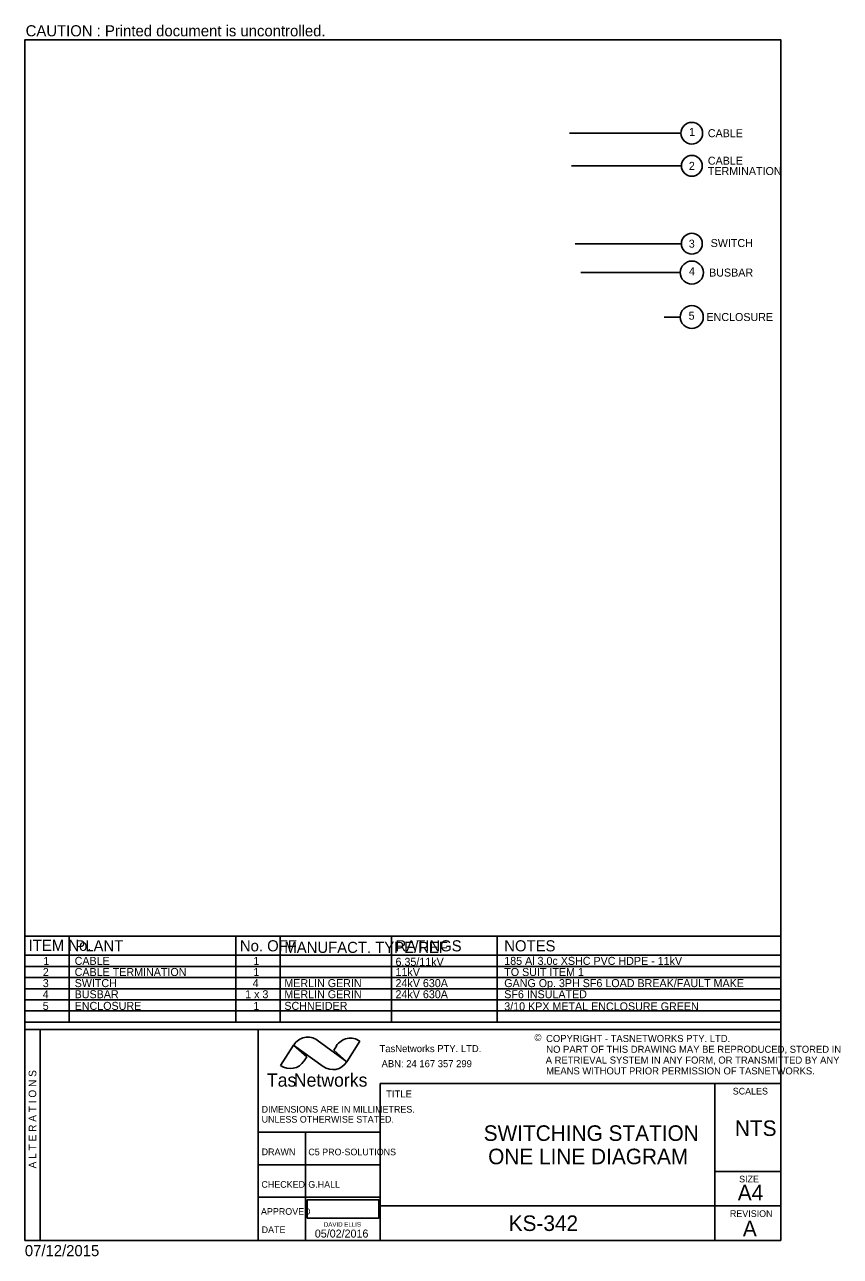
# Model space of a CAD drawing. Extents: x -190 to -7, y 10 to 287.
import ezdxf

# ---------------------------------------------------------------- set-up
doc = ezdxf.new("R2010")
doc.units = 0
for name, color, linetype in [('A4 BORDER TITLE BLOCK', 7, 'Continuous'), ('Default', 7, 'Continuous'), ('DRAWING', 7, 'Continuous')]:
    doc.layers.add(name, color=color, linetype=linetype)

# ---------------------------------------------------------------- blocks, each defined once
blk = doc.blocks.new('POINT_DISPLAY')
at = {"layer": 'Default'}
blk.add_line((0, 0), (0, 0), dxfattribs=at)
blk = doc.blocks.new('David Ellis')
at = {"layer": 'Default'}
blk.add_lwpolyline([(0.38, 5.03), (16.52, 5.03), (16.52, 9.1), (0.38, 9.1)], close=True, dxfattribs=at)
for s, height, p in [('DAVID ELLIS', 1, (4.15, 3.1)), ('05/02/2016', 1.8, (2.12, 0.65))]:
    blk.add_text(s, height=height, dxfattribs=at).set_placement(p)

msp = doc.modelspace()

# ---------------------------------------------------------------- linework, layer by layer
at = {"layer": 'A4 BORDER TITLE BLOCK'}
for p, q in [((-20, 60.93), (-190, 60.93)), ((-186.58, 13.5), (-186.58, 60.93)), ((-137.52, 13.5), (-137.52, 60.93)), ((-117.6, 53.69), (-124.25, 58.52)), ((-117.6, 53.69), (-124.25, 58.52)), ((-117.6, 53.69), (-124.25, 58.52)), ((-117.6, 53.69), (-114.66, 58.29)), ((-117.6, 53.69), (-114.66, 58.29)), ((-117.6, 53.69), (-114.66, 58.29)), ((-129.55, 57.45), (-132.49, 52.85)), ((-129.55, 57.45), (-132.49, 52.85)), ((-129.55, 57.45), (-132.49, 52.85)), ((-129.55, 57.45), (-122.9, 52.62)), ((-129.55, 57.45), (-126.61, 54.82)), ((-126.61, 54.82), (-129.55, 57.45)), ((-129.55, 57.45), (-122.9, 52.62)), ((-129.55, 57.45), (-122.9, 52.62)), ((-129.55, 57.45), (-126.61, 54.82)), ((-119.95, 57.22), (-120.53, 56.32)), ((-119.95, 57.22), (-120.53, 56.32)), ((-119.95, 57.22), (-120.53, 56.32)), ((-120.53, 56.32), (-117.6, 53.69)), ((-120.53, 56.32), (-117.6, 53.69)), ((-120.53, 56.32), (-117.6, 53.69)), ((-127.19, 53.92), (-126.61, 54.82)), ((-127.19, 53.92), (-126.61, 54.82)), ((-127.19, 53.92), (-126.61, 54.82)), ((-110.13, 48.77), (-20, 48.77)), ((-110.13, 48.77), (-110.13, 13.5)), ((-34.83, 13.5), (-34.83, 48.77)), ((-137.52, 37.82), (-110.13, 37.82)), ((-126.91, 37.82), (-126.91, 13.5)), ((-137.52, 30.53), (-110.13, 30.53)), ((-34.83, 29.02), (-20, 29.02)), ((-137.52, 23.23), (-110.13, 23.23)), ((-34.83, 21.26), (-110.13, 21.26)), ((-34.83, 21.26), (-20, 21.26)), ((-20, 13.5), (-190, 13.5))]:
    msp.add_line(p, q, dxfattribs=at)
msp.add_lwpolyline([(-190, 13.5), (-190, 283.5), (-20, 283.5), (-20, 13.5)], dxfattribs=at)
for centre, start_param, end_param in [((-126.39, 55.16), 5.685005, 7.255802), ((-126.39, 55.16), 5.685005, 7.255802), ((-126.39, 55.16), 5.685005, 7.255802), ((-116.8, 54.93), 5.685005, 7.255802), ((-116.8, 54.93), 5.685005, 7.255802), ((-116.8, 54.93), 5.685005, 7.255802), ((-130.34, 56.21), 2.543413, 4.114209), ((-130.34, 56.21), 2.543413, 4.114209), ((-130.34, 56.21), 2.543413, 4.114209), ((-120.75, 55.98), 2.543413, 4.114209), ((-120.75, 55.98), 2.543413, 4.114209), ((-120.75, 55.98), 2.543413, 4.114209)]:
    msp.add_ellipse(centre, major_axis=(0, 4.07), ratio=0.938106, start_param=start_param, end_param=end_param, dxfattribs=at)
at = {"layer": 'Default'}
for p, q in [((-42.44, 262.5), (-67.5, 262.5)), ((-42.34, 255.16), (-67.04, 255.16)), ((-42.35, 237.65), (-66.25, 237.65)), ((-42.59, 231.16), (-65, 231.16)), ((-42.59, 221.16), (-46.25, 221.16)), ((-180.05, 81.9), (-180.05, 62.62)), ((-142.55, 81.9), (-142.55, 62.62)), ((-132.55, 81.9), (-132.55, 62.62)), ((-107.55, 81.9), (-107.55, 62.62)), ((-83.8, 81.9), (-83.8, 62.62))]:
    msp.add_line(p, q, dxfattribs=at)
for centre, radius in [((-40.01, 262.5), 2.43), ((-40, 255.16), 2.34), ((-40, 237.65), 2.35), ((-40, 231.16), 2.59), ((-40.01, 221.16), 2.58)]:
    msp.add_circle(centre, radius, dxfattribs=at)
at = {"layer": 'DRAWING'}
for p, q in [((-190.05, 81.9), (-20.05, 81.9)), ((-190.05, 77.62), (-20.05, 77.62)), ((-190.05, 75.12), (-20.05, 75.12)), ((-190.05, 72.62), (-20.05, 72.62)), ((-190.05, 70.12), (-20.05, 70.12)), ((-190.05, 67.62), (-20.05, 67.62)), ((-190.05, 65.12), (-20.05, 65.12)), ((-190.05, 62.62), (-20.05, 62.62))]:
    msp.add_line(p, q, dxfattribs=at)

# ---------------------------------------------------------------- block references
at = {"layer": 'A4 BORDER TITLE BLOCK', "xscale": 1.7000000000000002, "yscale": 1.5882352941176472}
msp.add_blockref('POINT_DISPLAY', (-132.03, 52.53), dxfattribs=at)
msp.add_blockref('POINT_DISPLAY', (-132.03, 52.53), dxfattribs=at)
at = {"layer": 'Default'}
msp.add_blockref('David Ellis', (-126.91, 13.5), dxfattribs=at)

# ---------------------------------------------------------------- texts
at = {"layer": 'A4 BORDER TITLE BLOCK'}
for s, height, p in [('CAUTION : Printed document is uncontrolled.', 2.5, (-189.82, 284.28)), ('©', 1.59, (-75.39, 58.35)), ('COPYRIGHT - TASNETWORKS PTY. LTD.', 1.5882, (-72.78, 58.13)), ('TasNetworks PTY. LTD.', 1.5882, (-110.24, 55.85)), ('NO PART OF THIS DRAWING MAY BE REPRODUCED, STORED IN', 1.5882, (-72.74, 55.7)), ('ABN: 24 167 357 299', 1.5882, (-109.78, 52.46)), ('A RETRIEVAL SYSTEM IN ANY FORM, OR TRANSMITTED BY ANY', 1.5882, (-72.87, 53.27)), ('Tas', 2.97, (-135.57, 48.08)), ('Networks', 2.97, (-129.51, 48.08)), ('MEANS WITHOUT PRIOR PERMISSION OF TASNETWORKS.', 1.5882, (-72.76, 50.84)), ('TITLE', 1.588, (-108.75, 45.66)), ('SCALES', 1.5, (-30.8, 46.32)), ('DIMENSIONS ARE IN MILLIMETRES.', 1.5, (-136.75, 42.25)), ('UNLESS OTHERWISE STATED.', 1.5, (-136.75, 40)), ('SWITCHING STATION', 3.5, (-86.81, 35.89)), ('NTS', 3.5, (-30.32, 37)), ('DRAWN', 1.5, (-136.75, 32.68)), ('C5 PRO-SOLUTIONS', 1.5, (-126.25, 32.65)), ('ONE LINE DIAGRAM', 3.5, (-85.81, 30.64)), ('SIZE', 1.5, (-29.37, 26.55)), ('CHECKED', 1.5, (-136.8, 25.35)), ('G.HALL', 1.5, (-126.25, 25.35)), ('A4 ', 3.5, (-29.67, 22.51)), ('APPROVED', 1.5, (-136.9, 19.27)), ('REVISION', 1.5, (-31.44, 18.79)), ('DATE', 1.5, (-136.75, 15.16)), ('KS-342', 3.5, (-81.19, 15.63)), ('A', 3.5, (-28.53, 14.45)), ('07/12/2015', 2.5, (-190, 9.96))]:
    msp.add_text(s, height=height, dxfattribs=at).set_placement(p)
msp.add_text('A L T E R A T I O N S', height=1.7, rotation=90, dxfattribs=at).set_placement((-187.44, 29.7))
at = {"layer": 'Default'}
for s, p in [('1', (-40.61, 261.9)), ('2', (-40.67, 254.25)), ('3', (-40.69, 236.76)), ('4', (-40.65, 230.56)), ('5', (-40.72, 220.56))]:
    msp.add_text(s, height=1.8, dxfattribs=at).set_placement(p)
at = {"layer": 'DRAWING'}
for s, height, p in [('CABLE', 1.8, (-36.41, 261.6)), ('TERMINATION', 1.8, (-36.4, 253.09)), ('CABLE ', 1.8, (-36.4, 255.42)), ('SWITCH', 1.8, (-35.77, 236.9)), ('BUSBAR', 1.8, (-36.12, 230.26)), ('ENCLOSURE', 1.8, (-36.71, 220.26)), ('ITEM No.', 2.5, (-189.14, 78.62)), ('PLANT', 2.5, (-178.64, 78.51)), ('No. OFF', 2.5, (-141.64, 78.51)), ('MANUFACT. TYPE/REF', 2.5, (-131.64, 78.16)), ('RATINGS', 2.5, (-106.64, 78.51)), ('NOTES', 2.5, (-82.19, 78.51)), ('2', 1.8, (-185.96, 72.97)), ('1', 1.8, (-185.83, 75.47)), ('CABLE', 1.8, (-178.8, 75.47)), ('CABLE TERMINATION', 1.8, (-178.8, 72.97)), ('1', 1.8, (-138.61, 75.47)), ('6.35/11kV', 1.8, (-106.64, 75.26)), ('11kV', 1.8, (-106.64, 72.97)), ('TO SUIT ITEM 1', 1.8, (-82.19, 72.97)), ('185 Al 3.0c XSHC PVC HDPE - 11kV', 1.8, (-82.19, 75.47)), ('3', 1.8, (-185.97, 70.47)), ('SWITCH', 1.8, (-178.8, 70.47)), ('4', 1.8, (-138.76, 70.47)), ('1', 1.8, (-138.61, 72.97)), ('MERLIN GERIN', 1.8, (-131.64, 70.47)), ('24kV 630A', 1.8, (-106.64, 70.47)), ('GANG Op. 3PH SF6 LOAD BREAK/FAULT MAKE', 1.8, (-82.19, 70.47)), ('4', 1.8, (-185.97, 67.97)), ('BUSBAR', 1.8, (-178.8, 67.97)), ('1 x 3', 1.8, (-140.45, 67.97)), ('MERLIN GERIN', 1.8, (-131.64, 67.97)), ('24kV 630A', 1.8, (-106.64, 67.97)), ('SF6 INSULATED', 1.8, (-82.19, 67.97)), ('5', 1.8, (-185.98, 65.35)), ('ENCLOSURE', 1.8, (-178.8, 65.35)), ('1', 1.8, (-138.61, 65.35)), ('SCHNEIDER', 1.8, (-131.64, 65.35)), ('3/10 KPX METAL ENCLOSURE GREEN', 1.8, (-82.19, 65.24))]:
    msp.add_text(s, height=height, dxfattribs=at).set_placement(p)

doc.saveas('drawing.dxf')
